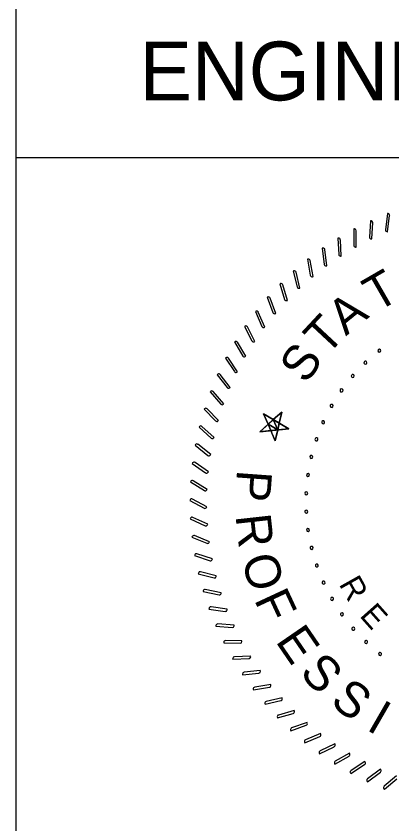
# Model space of a CAD drawing. Extents: x 0 to 34, y 0 to 22.
# Drawn here: x 9.25 to 10.338, y 1.322 to 3.659 of the extents above; entities that cross this region are included whole.
import ezdxf

# ---------------------------------------------------------------- set-up
doc = ezdxf.new("R2010")
doc.units = 0
doc.layers.add('Default', color=7, linetype='Continuous')
doc.layers.add('SH_Data', color=7, linetype='Continuous')

msp = doc.modelspace()

# ---------------------------------------------------------------- linework, layer by layer
at = {"layer": 'Default'}
for p, q in [((10.0187, 2.5131), (9.9551, 2.4568)), ((10.0396, 2.465), (9.9665, 2.508)), ((9.9665, 2.508), (10.0003, 2.4302)), ((10.0003, 2.4302), (10.0187, 2.5131)), ((9.9794, 2.4783), (10.0074, 2.4619)), ((10.0074, 2.4619), (9.9944, 2.4916)), ((9.9551, 2.4568), (10.0396, 2.465))]:
    msp.add_line(p, q, dxfattribs=at)
for points in [[(10.3269, 3.0875), (10.325, 3.0878), (10.3191, 3.0409)], [(10.2776, 3.0669), (10.2757, 3.067), (10.2726, 3.0198)], [(10.2793, 3.0143), (10.2824, 3.0615)], [(10.3255, 3.0349), (10.3313, 3.0818)], [(10.2296, 3.0433), (10.2277, 3.0433), (10.2275, 2.996)], [(10.2345, 2.9909), (10.2347, 3.0382)], [(10.1831, 3.0169), (10.1812, 3.0168), (10.1838, 2.9696)], [(10.2774, 3.0144), (10.2793, 3.0143)], [(10.3236, 3.0352), (10.3255, 3.0349)], [(10.1911, 2.9649), (10.1885, 3.0121)], [(10.2325, 2.9909), (10.2345, 2.9909)], [(10.1383, 2.9878), (10.1363, 2.9876), (10.1418, 2.9406)], [(10.1494, 2.9364), (10.1439, 2.9833)], [(10.0953, 2.956), (10.0934, 2.9557), (10.1016, 2.9092)], [(10.1094, 2.9054), (10.1012, 2.9519)], [(10.1892, 2.9648), (10.1911, 2.9649)], [(10.0543, 2.9218), (10.0523, 2.9213), (10.0633, 2.8753)], [(10.1474, 2.9362), (10.1494, 2.9364)], [(10.0714, 2.8721), (10.0604, 2.918)], [(10.1075, 2.905), (10.1094, 2.9054)], [(10.0153, 2.8851), (10.0135, 2.8845), (10.0272, 2.8393)], [(10.0354, 2.8365), (10.0217, 2.8817)], [(10.0695, 2.8716), (10.0714, 2.8721)], [(9.9787, 2.8462), (9.9768, 2.8455), (9.9933, 2.8012)], [(10.0016, 2.7989), (9.9852, 2.8432)], [(10.0335, 2.8359), (10.0354, 2.8365)], [(9.9444, 2.8051), (9.9426, 2.8044), (9.9617, 2.7611)], [(9.9702, 2.7593), (9.9511, 2.8025)], [(9.9998, 2.7982), (10.0016, 2.7989)], [(9.9127, 2.7621), (9.9109, 2.7612), (9.9325, 2.7192)], [(9.9411, 2.7179), (9.9195, 2.7599)], [(9.9684, 2.7585), (9.9702, 2.7593)], [(9.8836, 2.7173), (9.8819, 2.7163), (9.906, 2.6756)], [(9.9146, 2.6748), (9.8905, 2.7155)], [(9.9394, 2.717), (9.9411, 2.7179)], [(9.8572, 2.6708), (9.8556, 2.6697), (9.882, 2.6305)], [(9.8907, 2.6303), (9.8643, 2.6694)], [(9.9129, 2.6738), (9.9146, 2.6748)], [(9.8337, 2.6228), (9.8321, 2.6216), (9.8608, 2.5841)], [(9.8695, 2.5843), (9.8408, 2.6219)], [(9.8891, 2.6292), (9.8907, 2.6303)], [(9.813, 2.5735), (9.8115, 2.5722), (9.8425, 2.5365)], [(9.8511, 2.5372), (9.8202, 2.573)], [(9.868, 2.5831), (9.8695, 2.5843)], [(9.8496, 2.536), (9.8511, 2.5372)], [(9.7954, 2.523), (9.794, 2.5216), (9.827, 2.4878)], [(9.8356, 2.4891), (9.8026, 2.5229)], [(9.8342, 2.4877), (9.8356, 2.4891)], [(9.7808, 2.4716), (9.7794, 2.4701), (9.8144, 2.4384)], [(9.8229, 2.4402), (9.7879, 2.4719)], [(9.8216, 2.4387), (9.8229, 2.4402)], [(9.7693, 2.4194), (9.768, 2.4178), (9.8049, 2.3882)], [(9.8132, 2.3905), (9.7764, 2.4202)], [(9.812, 2.389), (9.8132, 2.3905)], [(9.7609, 2.3666), (9.7598, 2.365), (9.7983, 2.3376)], [(9.8065, 2.3404), (9.768, 2.3678)], [(9.8054, 2.3388), (9.8065, 2.3404)], [(9.7557, 2.3134), (9.7547, 2.3117), (9.7948, 2.2867)], [(9.8028, 2.29), (9.7627, 2.315)], [(9.8018, 2.2883), (9.8028, 2.29)], [(9.7537, 2.2599), (9.7528, 2.2582), (9.7943, 2.2356)], [(9.8021, 2.2394), (9.7606, 2.262)], [(9.8012, 2.2377), (9.8021, 2.2394)], [(9.7549, 2.2065), (9.7541, 2.2047), (9.7969, 2.1847)], [(9.8045, 2.1889), (9.7617, 2.2089)], [(9.8037, 2.1871), (9.8045, 2.1889)], [(9.7593, 2.1532), (9.7586, 2.1514), (9.8025, 2.1339)], [(9.8099, 2.1386), (9.7659, 2.1561)], [(9.8091, 2.1368), (9.8099, 2.1386)], [(9.8182, 2.0887), (9.7733, 2.1035)], [(9.7669, 2.1003), (9.7663, 2.0984), (9.8112, 2.0836)], [(9.8176, 2.0869), (9.8182, 2.0887)], [(9.7776, 2.0479), (9.7771, 2.046), (9.8228, 2.0339)], [(9.8295, 2.0394), (9.7839, 2.0515)], [(9.829, 2.0375), (9.8295, 2.0394)], [(9.7915, 1.9963), (9.7911, 1.9943), (9.8374, 1.985)], [(9.8438, 1.9909), (9.7975, 2.0003)], [(9.8434, 1.989), (9.8438, 1.9909)], [(9.8084, 1.9456), (9.8081, 1.9436), (9.8549, 1.9371)], [(9.8609, 1.9434), (9.8141, 1.9499)], [(9.8607, 1.9414), (9.8609, 1.9434)], [(9.8283, 1.8959), (9.8281, 1.894), (9.8753, 1.8902)], [(9.8809, 1.8969), (9.8338, 1.9006)], [(9.8807, 1.8949), (9.8809, 1.8969)], [(9.8511, 1.8476), (9.8511, 1.8456), (9.8984, 1.8447)], [(9.9036, 1.8517), (9.8563, 1.8526)], [(9.9035, 1.8497), (9.9036, 1.8517)], [(9.8768, 1.8007), (9.8769, 1.7988), (9.9241, 1.8007)], [(9.9289, 1.8079), (9.8817, 1.806)], [(9.929, 1.806), (9.9289, 1.8079)], [(9.9053, 1.7555), (9.9055, 1.7535), (9.9525, 1.7582)], [(9.9568, 1.7658), (9.9098, 1.761)], [(9.957, 1.7638), (9.9568, 1.7658)], [(9.9364, 1.712), (9.9367, 1.71), (9.9834, 1.7176)], [(9.9872, 1.7254), (9.9406, 1.7178)], [(9.9876, 1.7234), (9.9872, 1.7254)], [(10.02, 1.6868), (9.9739, 1.6765)], [(10.0204, 1.6849), (10.02, 1.6868)], [(9.97, 1.6704), (9.9705, 1.6685), (10.0166, 1.6788)], [(10.0061, 1.631), (10.0067, 1.6291), (10.0521, 1.6421)], [(10.055, 1.6503), (10.0096, 1.6373)], [(10.0556, 1.6484), (10.055, 1.6503)], [(10.0921, 1.616), (10.0476, 1.6002)], [(10.0928, 1.6141), (10.0921, 1.616)], [(10.0445, 1.5938), (10.0451, 1.5919), (10.0897, 1.6076)], [(10.085, 1.5589), (10.0858, 1.5571), (10.1293, 1.5755)], [(10.1312, 1.5839), (10.0877, 1.5655)], [(10.132, 1.5821), (10.1312, 1.5839)], [(10.1275, 1.5265), (10.1284, 1.5247), (10.1708, 1.5457)], [(10.1722, 1.5543), (10.1298, 1.5333)], [(10.1731, 1.5525), (10.1722, 1.5543)], [(10.2149, 1.5271), (10.1738, 1.5037)], [(10.2158, 1.5254), (10.2149, 1.5271)], [(10.1719, 1.4967), (10.1729, 1.495), (10.2139, 1.5185)], [(10.2591, 1.5026), (10.2195, 1.4767)], [(10.2601, 1.5009), (10.2591, 1.5026)], [(10.218, 1.4697), (10.2191, 1.468), (10.2587, 1.4939)], [(10.2657, 1.4454), (10.2669, 1.4438), (10.3048, 1.472)], [(10.3047, 1.4807), (10.2667, 1.4525)], [(10.3058, 1.4791), (10.3047, 1.4807)], [(10.3147, 1.424), (10.3159, 1.4225), (10.3521, 1.4529)], [(10.3515, 1.4616), (10.3153, 1.4312)]]:
    msp.add_lwpolyline(points, dxfattribs=at)
for points in [[(9.9794, 2.4783), (9.9665, 2.508), (9.9944, 2.4916), (9.9944, 2.4916)], [(9.9665, 2.508), (9.9944, 2.4916), (9.9665, 2.508), (9.9794, 2.4783)], [(10.0117, 2.4814), (10.0187, 2.5131), (9.9944, 2.4916), (9.9944, 2.4916)], [(10.0187, 2.5131), (9.9944, 2.4916), (10.0187, 2.5131), (10.0117, 2.4814)], [(9.9874, 2.4599), (9.9551, 2.4568), (9.9794, 2.4783), (9.9794, 2.4783)], [(9.9551, 2.4568), (9.9794, 2.4783), (9.9551, 2.4568), (9.9874, 2.4599)], [(9.9944, 2.4916), (9.9794, 2.4783), (10.0074, 2.4619), (10.0074, 2.4619)], [(9.9794, 2.4783), (10.0074, 2.4619), (9.9794, 2.4783), (9.9944, 2.4916)], [(9.9874, 2.4599), (9.9794, 2.4783), (10.0074, 2.4619), (10.0074, 2.4619)], [(9.9794, 2.4783), (10.0074, 2.4619), (9.9794, 2.4783), (9.9874, 2.4599)], [(9.9944, 2.4916), (10.0074, 2.4619), (10.0117, 2.4814), (10.0117, 2.4814)], [(10.0074, 2.4619), (10.0117, 2.4814), (10.0074, 2.4619), (9.9944, 2.4916)], [(10.0074, 2.4619), (10.0117, 2.4814), (10.0396, 2.465), (10.0396, 2.465)], [(10.0117, 2.4814), (10.0396, 2.465), (10.0117, 2.4814), (10.0074, 2.4619)], [(9.9874, 2.4599), (10.0074, 2.4619), (10.0003, 2.4302), (10.0003, 2.4302)], [(10.0074, 2.4619), (10.0003, 2.4302), (10.0074, 2.4619), (9.9874, 2.4599)]]:
    msp.add_lwpolyline(points, close=True, dxfattribs=at)
for centre, radius, start, end in [((10.3263, 3.0825), 0.00508, 352.9563, 82.9563), ((10.2773, 3.0618), 0.00508, 356.3849, 86.3849), ((10.2296, 3.0382), 0.00508, 359.8134, 89.8134), ((10.3242, 3.0402), 0.00508, 172.9563, 262.9563), ((10.1834, 3.0118), 0.00508, 3.242, 93.242), ((10.2777, 3.0195), 0.00508, 176.3849, 266.3849), ((10.2325, 2.996), 0.00508, 179.8134, 269.8134), ((10.1389, 2.9827), 0.00508, 6.6706, 96.6706), ((10.1889, 2.9699), 0.00508, 183.242, 273.242), ((10.0962, 2.951), 0.00508, 10.0992, 100.0992), ((10.0554, 2.9168), 0.00508, 13.5277, 103.5277), ((10.1468, 2.9412), 0.00508, 186.6706, 276.6706), ((10.1066, 2.91), 0.00508, 190.0992, 280.0992), ((10.0168, 2.8802), 0.00508, 16.9563, 106.9563), ((10.0683, 2.8765), 0.00508, 193.5277, 283.5277), ((9.9805, 2.8414), 0.00508, 20.3849, 110.3849), ((10.0321, 2.8408), 0.00508, 196.9563, 286.9563), ((9.9465, 2.8005), 0.00508, 23.8134, 113.8134), ((9.998, 2.803), 0.00508, 200.3849, 290.3849), ((9.915, 2.7576), 0.00508, 27.242, 117.242), ((9.9663, 2.7631), 0.00508, 203.8134, 293.8134), ((9.8862, 2.7129), 0.00508, 30.6706, 120.6706), ((9.9371, 2.7215), 0.00508, 207.242, 297.242), ((10.3012, 2.6912), 0.00437, 38.1818, 218.1818), ((10.3012, 2.6912), 0.00437, 218.1818, 38.1818), ((9.8601, 2.6666), 0.00508, 34.0992, 124.0992), ((9.9103, 2.6782), 0.00508, 210.6706, 300.6706), ((10.2612, 2.6564), 0.00437, 43.6364, 223.6364), ((10.2612, 2.6564), 0.00437, 223.6364, 43.6364), ((9.8367, 2.6188), 0.00508, 37.5277, 127.5277), ((9.8862, 2.6334), 0.00508, 214.0992, 304.0992), ((10.2246, 2.6178), 0.00437, 49.0909, 229.0909), ((10.2246, 2.6178), 0.00437, 229.0909, 49.0909), ((9.8163, 2.5696), 0.00508, 40.9563, 130.9563), ((9.8649, 2.5872), 0.00508, 217.5277, 307.5277), ((10.1919, 2.576), 0.00437, 54.5455, 234.5455), ((10.1919, 2.576), 0.00437, 234.5455, 54.5455), ((9.7989, 2.5194), 0.00508, 44.3849, 134.3849), ((9.8463, 2.5398), 0.00508, 220.9563, 310.9563), ((10.1633, 2.5313), 0.00437, 60, 240), ((10.1633, 2.5313), 0.00437, 240, 60), ((9.8306, 2.4914), 0.00508, 224.3849, 314.3849), ((10.139, 2.484), 0.00437, 65.4545, 245.4545), ((10.139, 2.484), 0.00437, 245.4545, 65.4545), ((9.7845, 2.4682), 0.00508, 47.8134, 137.8134), ((9.8178, 2.4421), 0.00508, 227.8134, 317.8134), ((10.1194, 2.4347), 0.00437, 70.9091, 250.9091), ((10.1194, 2.4347), 0.00437, 250.9091, 70.9091), ((9.7732, 2.4162), 0.00508, 51.242, 141.242), ((9.808, 2.3922), 0.00508, 231.242, 321.242), ((10.1046, 2.3837), 0.00437, 76.3636, 256.3636), ((10.1046, 2.3837), 0.00437, 256.3636, 76.3636), ((9.7651, 2.3636), 0.00508, 54.6706, 144.6706), ((9.8012, 2.3417), 0.00508, 234.6706, 324.6706), ((9.76, 2.3107), 0.00508, 58.0992, 148.0992), ((10.0947, 2.3315), 0.00437, 81.8182, 261.8182), ((10.0947, 2.3315), 0.00437, 261.8182, 81.8182), ((9.7975, 2.291), 0.00508, 238.0992, 328.0992), ((10.0897, 2.2786), 0.00437, 87.2727, 267.2727), ((10.0897, 2.2786), 0.00437, 267.2727, 87.2727), ((9.7582, 2.2575), 0.00508, 61.5277, 151.5277), ((9.7967, 2.2401), 0.00508, 241.5277, 331.5277), ((10.0899, 2.2255), 0.00437, 92.7273, 272.7273), ((10.0899, 2.2255), 0.00437, 272.7273, 92.7273), ((9.7595, 2.2043), 0.00508, 64.9563, 154.9563), ((9.7991, 2.1893), 0.00508, 244.9563, 334.9563), ((10.095, 2.1726), 0.00437, 98.1818, 278.1818), ((10.095, 2.1726), 0.00437, 278.1818, 98.1818), ((9.7641, 2.1513), 0.00508, 68.3849, 158.3849), ((9.8044, 2.1387), 0.00508, 248.3849, 338.3849), ((9.7717, 2.0987), 0.00508, 71.8134, 161.8134), ((10.1052, 2.1205), 0.00437, 103.6364, 283.6364), ((10.1052, 2.1205), 0.00437, 283.6364, 103.6364), ((9.8128, 2.0885), 0.00508, 251.8134, 341.8134), ((10.1203, 2.0696), 0.00437, 109.0909, 289.0909), ((10.1203, 2.0696), 0.00437, 289.0909, 109.0909), ((9.7826, 2.0466), 0.00508, 75.242, 165.242), ((9.8241, 2.0388), 0.00508, 255.242, 345.242), ((10.1401, 2.0203), 0.00437, 114.5455, 294.5455), ((10.1401, 2.0203), 0.00437, 294.5455, 114.5455), ((9.7965, 1.9953), 0.00508, 78.6706, 168.6706), ((9.8384, 1.99), 0.00508, 258.6706, 348.6706), ((10.1646, 1.9732), 0.00437, 120, 300), ((10.1646, 1.9732), 0.00437, 300, 120), ((9.8134, 1.9449), 0.00508, 82.0992, 172.0992), ((9.8556, 1.9421), 0.00508, 262.0992, 352.0992), ((10.1934, 1.9286), 0.00437, 125.4545, 305.4545), ((10.1934, 1.9286), 0.00437, 305.4545, 125.4545), ((9.8334, 1.8955), 0.00508, 85.5277, 175.5277), ((9.8757, 1.8953), 0.00508, 265.5277, 355.5277), ((10.2263, 1.8869), 0.00437, 130.9091, 310.9091), ((10.2263, 1.8869), 0.00437, 310.9091, 130.9091), ((9.8562, 1.8475), 0.00508, 88.9563, 178.9563), ((9.8985, 1.8498), 0.00508, 268.9563, 358.9563), ((10.2631, 1.8486), 0.00437, 136.3636, 316.3636), ((10.2631, 1.8486), 0.00437, 316.3636, 136.3636), ((9.8819, 1.8009), 0.00508, 92.3849, 182.3849), ((9.9239, 1.8058), 0.00508, 272.3849, 2.3849), ((10.3033, 1.8139), 0.00437, 141.8182, 321.8182), ((10.3033, 1.8139), 0.00437, 321.8182, 141.8182), ((9.9103, 1.756), 0.00508, 95.8134, 185.8134), ((9.952, 1.7633), 0.00508, 275.8134, 5.8134), ((9.9414, 1.7128), 0.00508, 99.242, 189.242), ((9.9825, 1.7226), 0.00508, 279.242, 9.242), ((10.0155, 1.6838), 0.00508, 282.6706, 12.6706), ((9.975, 1.6716), 0.00508, 102.6706, 192.6706), ((10.011, 1.6324), 0.00508, 106.0992, 196.0992), ((10.0507, 1.647), 0.00508, 286.0992, 16.0992), ((10.088, 1.6124), 0.00508, 289.5277, 19.5277), ((10.0493, 1.5955), 0.00508, 109.5277, 199.5277), ((10.0897, 1.5609), 0.00508, 112.9563, 202.9563), ((10.1273, 1.5801), 0.00508, 292.9563, 22.9563), ((10.1685, 1.5503), 0.00508, 296.3849, 26.3849), ((10.1321, 1.5288), 0.00508, 116.3849, 206.3849), ((10.2114, 1.5229), 0.00508, 299.8134, 29.8134), ((10.1764, 1.4993), 0.00508, 119.8134, 209.8134), ((10.2559, 1.4981), 0.00508, 303.242, 33.242), ((10.2223, 1.4724), 0.00508, 123.242, 213.242), ((10.3018, 1.4761), 0.00508, 306.6706, 36.6706), ((10.2698, 1.4484), 0.00508, 126.6706, 216.6706), ((10.3186, 1.4273), 0.00508, 130.0992, 220.0992)]:
    msp.add_arc(centre, radius, start, end, dxfattribs=at)
at = {"layer": 'SH_Data'}
for p, q in [((9.25, 0.5), (9.25, 3.75)), ((9.25, 3.25), (12.05, 3.25))]:
    msp.add_line(p, q, dxfattribs=at)

# ---------------------------------------------------------------- texts
at = {"layer": 'Default'}
for s, height, rotation, p in [('T', 0.1017, 30.0029, (10.2939, 2.801)), ('A', 0.1017, 39.086, (10.2046, 2.7324)), ('T', 0.1017, 47.0425, (10.1489, 2.6734)), ('S', 0.1017, 55.6603, (10.0901, 2.5918)), ('P', 0.1017, 265.8671, (9.8899, 2.3483)), ('R', 0.1017, 276.2702, (9.8848, 2.2142)), ('O', 0.1017, 285.6242, (9.9017, 2.0892)), ('R', 0.0661, 299.2651, (10.1831, 2.0159)), ('F', 0.1017, 294.8902, (9.9378, 1.9715)), ('E', 0.0661, 311.5858, (10.2421, 1.9236)), ('E', 0.1017, 304.4652, (9.999, 1.851)), ('S', 0.1017, 313.405, (10.0674, 1.7572)), ('S', 0.1017, 322.7431, (10.1556, 1.6697)), ('I', 0.1017, 329.9953, (10.2612, 1.5961))]:
    msp.add_text(s, height=height, rotation=rotation, dxfattribs=at).set_placement(p)
at = {"layer": 'SH_Data'}
msp.add_text('ENGINEERS SEAL:', height=0.17, dxfattribs=at).set_placement((9.6074, 3.415))

doc.saveas('drawing.dxf')
